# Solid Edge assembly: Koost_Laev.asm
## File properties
Author: User
Template: Iso Metric Assembly.asm
Last saved by: User
Revision: 15
Application: Solid Edge
Username: User
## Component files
06metal2.psm
07polt.par
01kere.par
02mast.par
03puri.par
04puri-2.par
05metal.psm
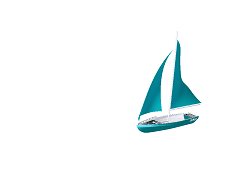
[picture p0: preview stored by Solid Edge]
